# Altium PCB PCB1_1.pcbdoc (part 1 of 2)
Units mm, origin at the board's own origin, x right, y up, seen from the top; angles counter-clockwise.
Board outline 93.4 x 134 mm, 2 copper layers (Top Layer, Bottom Layer); 92 components, 71 nets, 349 pads, 191 vias.
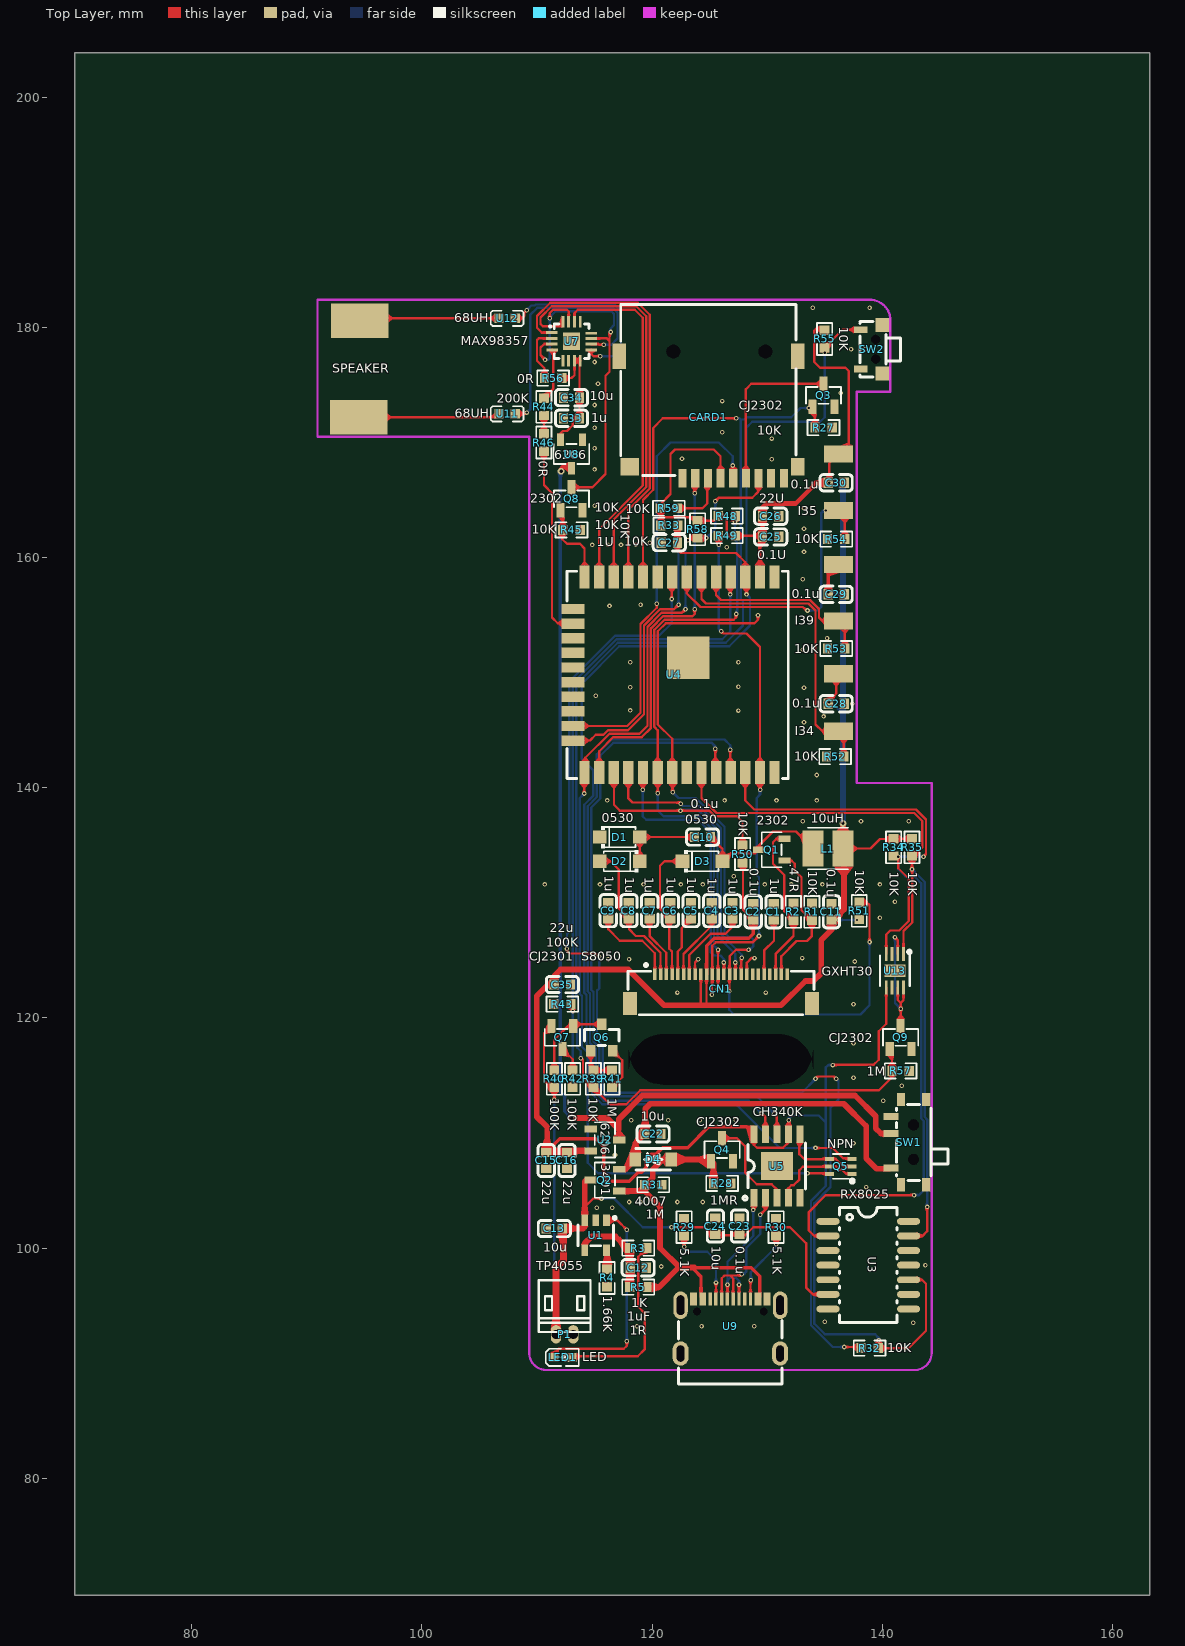
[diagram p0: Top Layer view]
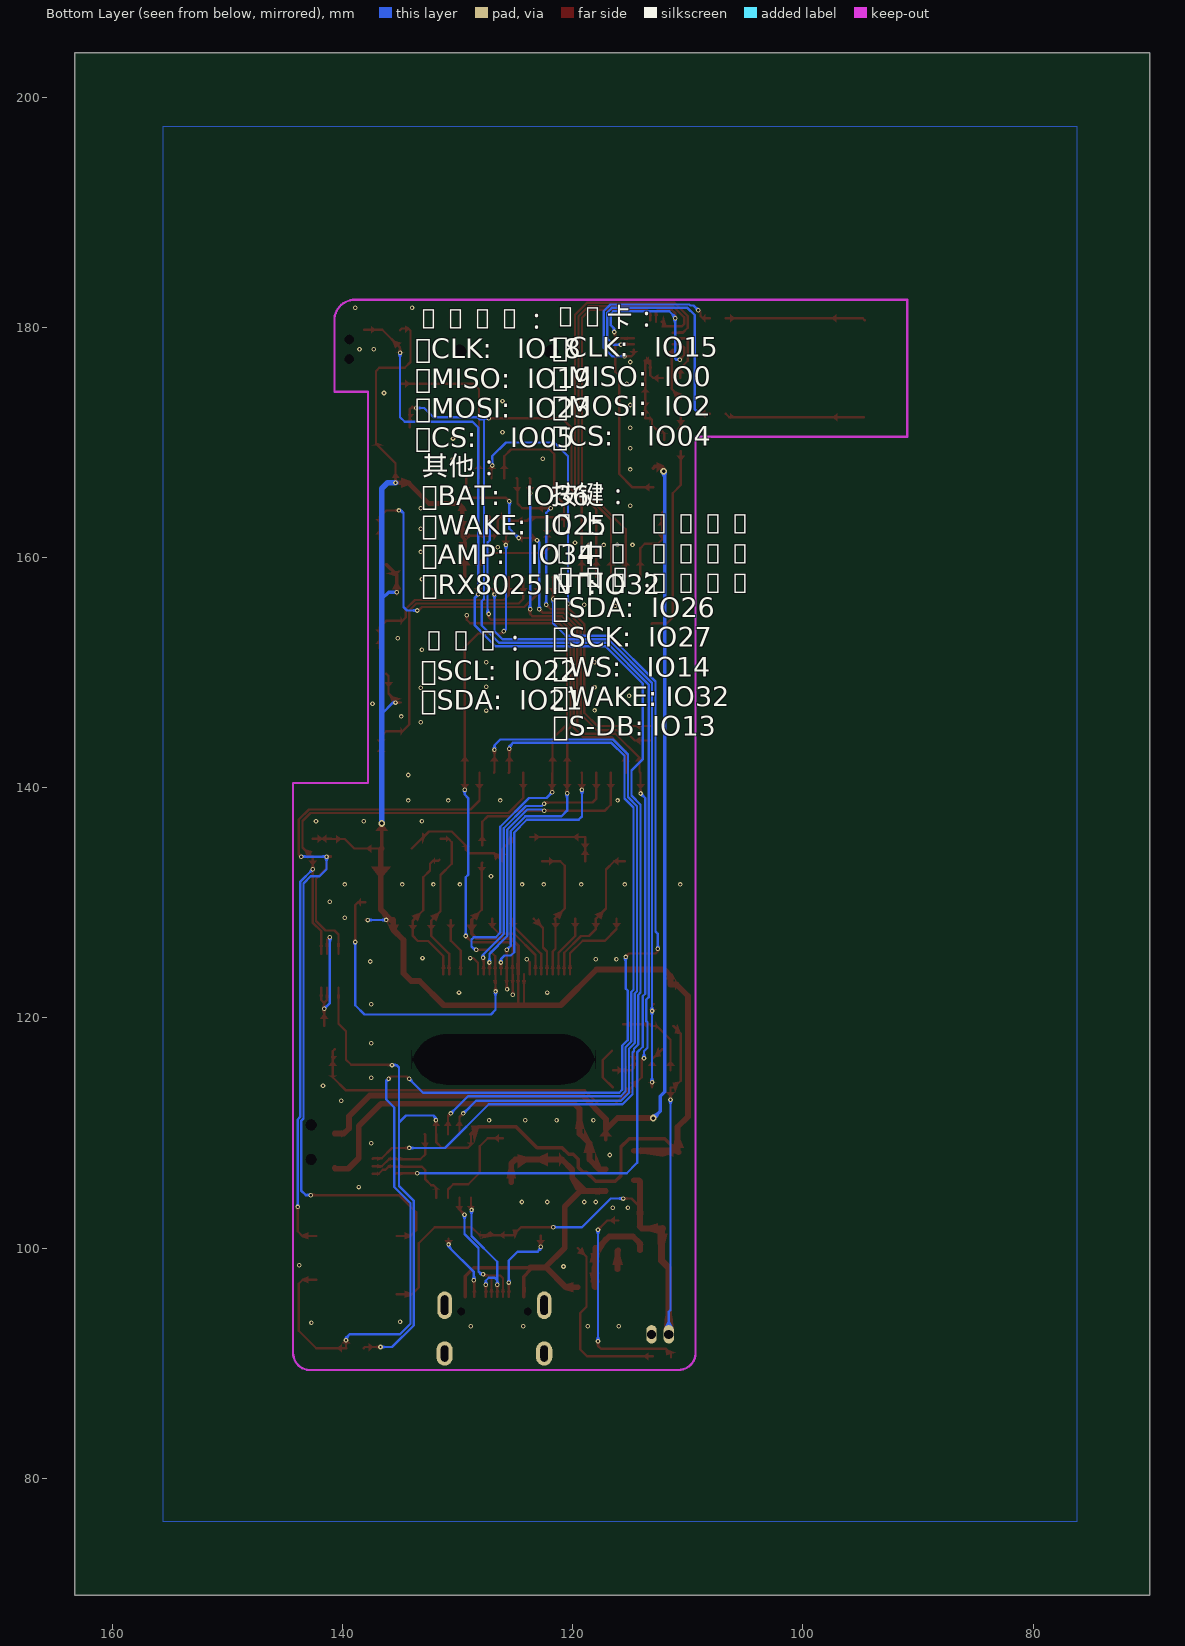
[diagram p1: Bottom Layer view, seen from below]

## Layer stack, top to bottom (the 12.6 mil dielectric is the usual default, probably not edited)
Top Layer: signal copper (thickness not stored)
Dielectric: dielectric 0.32, FR-4, Dk 4.8
Bottom Layer: signal copper (thickness not stored)

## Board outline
163.25,69.85 69.85,69.85 69.85,203.85 163.25,203.85
cut-out: 120.986,118.6 130.986,118.6 cw(c130.986,115.6) 133.986,115.6 133.986,117.2 cw(c130.986,117.2) 130.986,114.2 120.986,114.2 cw(c120.986,117.2) 117.986,117.2 117.986,115.6 cw(c120.986,115.6)

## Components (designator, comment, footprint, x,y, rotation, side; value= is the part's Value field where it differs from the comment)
C1 "CAP_0603" C0603 130.586,129.214 r270 top
C2 "CAP_0603" C0603 128.786,129.214 r270 top
C3 "CAP_0603" C0603 126.986,129.314 r270 top
C4 "CAP_0603" C0603 125.186,129.314 r270 top
C5 "CAP_0603" C0603 123.386,129.314 r270 top
C6 "CAP_0603" C0603 121.586,129.314 r270 top
C7 "CAP_0603" C0603 119.786,129.314 r270 top
C8 "CAP_0603" C0603 117.986,129.314 r270 top
C9 "CAP_0603" C0603 116.186,129.314 r270 top
C10 "CAP_0603" C0603 124.386,135.714 r180 top
C11 "CAP_0603" C0603 135.586,129.214 r270 top
C12 "CAP_0603" C0603 118.8,98.3 r0 top
C13 "CAP_0603" C0603 111.5,101.7 r180 top
C15 "CAP_0603" C0603 110.805,107.616 r90 top
C16 "CAP_0603" C0603 112.605,107.616 r90 top
C22 "CAP_0603" C0603 120.086,109.914 r180 top
C23 "CAP_0603" C0603 127.6,101.9 r270 top
C24 "CAP_0603" C0603 125.5,101.9 r270 top
C25 "CAP_0603" C0603 130.3,161.8 r180 top
C26 "CAP_0603" C0603 130.3,163.6 r180 top
C27 "CAP_0603" C0603 121.5,161.3 r0 top
C28 "CAP_0603" C0603 136,147.3 r0 top
C29 "CAP_0603" C0603 136,156.8 r0 top
C30 "CAP_0603" C0603 136,166.5 r0 top
C33 "CAP_0603" C0603 113,172.1 r0 top
C34 "CAP_0603" C0603 113,173.9 r0 top
C35 "CAP_0603" C0603 112.2,122.9 r180 top
CARD1 "XKTF-015-G" TF-SMD_XKTF-015-N 124.9,172.2 r180 top
CN1 "HW05150-240R00" FPC-SMD_24P-P0.50_HW05150-240R00 125.986,122.514 r0 top
D1 "MBR0530" SOD-123FL_L2.7-W1.8-LS3.7-RD 117.186,135.714 r0 top
D2 "MBR0530" SOD-123FL_L2.7-W1.8-LS3.7-RD 117.186,133.614 r180 top
D3 "MBR0530" SOD-123FL_L2.7-W1.8-LS3.7-RD 124.386,133.614 r0 top
D4 "SM4007PL_C64898" SOD-123F_L2.8-W1.8-LS3.7-RD 120.1,107.7 r0 top
L1 "SCCD32-100KT" IND-SMD_L3.5-W3.0 135.286,134.714 r0 top
LED1 "LED_0603-B" LED_0603 112.3,90.5 r0 top
P1 "弯针1.25*2" CON1.5*2-90 112.4,92.5 r180 top
Q1 "SL2302" SOT-23-3_L3.0-W1.7-P0.95-LS2.9-BR 130.386,134.614 r0 top
Q2 "CJ3401" SOT-23-3_L2.9-W1.6-P1.90-LS2.8-BR 115.9,105.9 r0 top
Q3 "CJ2302" SOT-23-3_L2.9-W1.3-P1.90-LS2.4-BR 134.9,174.1 r270 top
Q4 "CJ2302" SOT-23-3_L2.9-W1.3-P1.90-LS2.4-BR 126.085,108.547 r270 top
Q5 "PUMH9,115" SOT-363_L2.0-W1.3-P0.65-LS2.1-BL 136.4,107.1 r90 top
Q6 "S8050_SOT_NPN" S8050_SOT-23 115.5,118.3 r270 top
Q7 "CJ2301" SOT-23-3_L2.9-W1.3-P1.90-LS2.4-BR 112.2,118.3 r90 top
Q8 "CJ2302" SOT-23-3_L2.9-W1.3-P1.90-LS2.4-BR 113,165.1 r270 top
Q9 "CJ2302" SOT-23-3_L2.9-W1.3-P1.90-LS2.4-BR 141.6,118.3 r270 top
R1 "Res_0603" R0603 133.886,129.214 r270 top
R2 "Res_0603" R0603 132.286,129.214 r270 top
R3 "Res_0603" R0603 118.8,100 r0 top
R4 "Res_0603" R0603 116.1,97.4 r270 top
R5 "Res_0603" R0603 118.8,96.6 r180 top
R27 "Res_0603" R0603 134.9,171.3 r0 top
R28 "Res_0603" R0603 126.086,105.614 r180 top
R29 "Res_0603" R0603 122.786,101.814 r270 top
R30 "Res_0603" R0603 130.786,101.814 r90 top
R31 "Res_0603" R0603 120.1,105.5 r180 top
R32 "Res_0603" R0603 138.9,91.3 r180 top
R33 "Res_0603" R0603 121.5,162.8 r0 top
R34 "Res_0603" R0603 140.986,134.814 r270 top
R35 "Res_0603" R0603 142.586,134.814 r270 top
R39 "Res_0603" R0603 114.9,114.7 r90 top
R40 "Res_0603" R0603 111.5,114.7 r90 top
R41 "Res_0603" R0603 116.5,114.7 r270 top
R42 "Res_0603" R0603 113.1,114.7 r270 top
R43 "Res_0603" R0603 112.2,121.2 r180 top
R44 "Res_0603" R0603 110.6,173.1 r90 top
R45 "Res_0603" R0603 113,162.4 r180 top
R46 "Res_0603" R0603 110.6,170 r270 top
R48 "Res_0603" R0603 126.5,163.6 r0 top
R49 "Res_0603" R0603 126.5,161.9 r180 top
R50 "Res_0603" R0603 127.859,134.24 r90 top
R51 "Res_0603" R0603 138,129.3 r90 top
R52 "Res_0603" R0603 135.9,142.7 r180 top
R53 "Res_0603" R0603 136,152.1 r180 top
R54 "Res_0603" R0603 136,161.6 r180 top
R55 "Res_0603" R0603 135,179 r270 top
R56 "Res_0603" R0603 111.4,175.6 r180 top
R57 "Res_0603" R0603 141.6,115.4 r0 top
R58 "Res_0603" R0603 123.959,162.461 r270 top
R59 "Res_0603" R0603 121.459,164.287 r0 top
SW1 "MSK12CO2-BDM" SW-SMD_MSK12CO2-BDM 142.3,109.2 r90 top
SW2 "TS-1010-C-A" KEY-SMD_TX-1010-X-X 139.1,178.1 r270 top
U1 "TP4055" SOT-23-5_L3.0-W1.7-P0.95-LS2.8-BR 115.1,101.1 r90 top
U2 "ME6206A33M3G" SOT-23-3_L2.9-W1.6-P1.90-LS2.8-BR 115.9,109.4 r180 top
U3 "RX8025T-UB" SOIC-14_L10.1-W5.0-P1.27-LS7.4-BL 138.786,98.514 r270 top
U4 "ESP32-WROOM-32UE-N4_C2934568" WIFI-SMD_ESP32-WROOM-32UE-A 121.886,149.814 r270 top
U5 "CH340K" ESOP-10_L4.9-W3.9-P1.00-LS6.2-BL-EP 130.843,107.131 r0 top
U7 "MAX98357AETE+T" TQFN-16_L3.0-W3.0-P0.50-BL-EP1.5 113,178.8 r270 top
U8 "ME6206A33M3G" SOT-23-3_L2.9-W1.6-P1.90-LS2.8-BR 113,169 r90 top
U9 "TYPE-C16PIN母座 板上四脚三次molding" USB-SMD_TYPE-C16PIN 126.8,93.2 r0 top
U11 "EBLS1608-3R9K" L0603 107.4,172.5 r180 top
U12 "EBLS1608-3R9K" L0603 107.4,180.8 r180 top
U13 "GXHT30" DFN-8_L2.5-W2.5-P0.50-BL-EP 141.1,124.1 r180 top

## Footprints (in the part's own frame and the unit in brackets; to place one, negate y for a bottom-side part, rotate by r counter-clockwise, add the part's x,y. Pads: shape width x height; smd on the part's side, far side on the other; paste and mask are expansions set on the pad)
C0603 [mm]
  rect 0.8x0.9 smd paste+0 mask+0.051: 1(-0.7,0) 2(0.7,0)
  silkscreen extent -1.41,-0.71 1.39,0.72
CON1.5*2-90 [mm]
  oval 0.9x1.6 hole 0.8 paste+0 mask+0.102: 1(-0.75,0) 2(0.75,0)
  silkscreen extent -2.25,-4.7 2.25,-0.2
DFN-8_L2.5-W2.5-P0.50-BL-EP [mm]
  rect 0.25x1.25 smd paste+0 mask+0.051: 1(-0.75,-1.454) 2(-0.25,-1.454) 3(0.25,-1.454) 4(0.75,-1.454) 5(0.75,1.454) 6(0.25,1.454) 7(-0.25,1.454) 8(-0.75,1.454)
  rect 1.8x1.1 smd paste+0 mask+0.051: 9(0,0)
  silkscreen extent -1.39,-1.77 1.3,1.3
ESOP-10_L4.9-W3.9-P1.00-LS6.2-BL-EP [mm]
  rect 0.6x1.5 smd paste+0 mask+0.051: 1(-2,-2.75) 2(-1,-2.75) 3(0,-2.75) 4(1,-2.75) 5(2,-2.75) 6(2,2.75) 7(1,2.75) 8(0,2.75) 9(-1,2.75) 10(-2,2.75)
  rect 2.8x2.4 smd paste+0 mask+0.051: 11(0,0)
  silkscreen extent -2.94,-2.96 2.5,2
FPC-SMD_24P-P0.50_HW05150-240R00 [mm]
  rect 0.3x1 smd paste+0 mask+0.05: 1(-5.75,1.275) 2(-5.25,1.275) 3(-4.75,1.275) 4(-4.25,1.275) 5(-3.75,1.275) 6(-3.25,1.275) 7(-2.75,1.275) 8(-2.25,1.275) 9(-1.75,1.275) 10(-1.25,1.275) 11(-0.75,1.275) 12(-0.25,1.275) 13(0.25,1.275) 14(0.75,1.275) 15(1.25,1.275) 16(1.75,1.275) 17(2.25,1.275) 18(2.752,1.275) 19(3.25,1.275) 20(3.75,1.275) 21(4.25,1.275) 22(4.75,1.275) 23(5.25,1.275) 24(5.75,1.275)
  rect 1.2x2 smd paste+0 mask+0.05: 25(7.9,-1.275) 26(-7.9,-1.275)
  silkscreen extent -8.09,-2.24 8.07,2.21
IND-SMD_L3.5-W3.0 [mm]
  rect 1.8x3.12 smd paste+0 mask+0.051: 1(1.303,0) 2(-1.303,0)
  silkscreen extent -1.75,-1.8 1.75,1.8
KEY-SMD_TX-1010-X-X [mm]
  rect 0.6x1.2 smd paste+0 mask+0.051: 1(-1.7,-0.975) 2(1.7,-0.975)
  rect 1.2x1.3 smd paste+0 mask+0.051: 3(-2.1,0.975) 4(2.1,0.975)
  Multi-Layer board cut-out: -0.85,0.725 -1.023,0.685 -1.163,0.574 -1.24,0.414 -1.24,0.236 -1.163,0.076 -1.023,-0.035 -0.85,-0.075 -0.85,-0.075 -0.676,-0.035 -0.537,0.076 -0.46,0.236 -0.46,0.414 -0.537,0.574 -0.676,0.685 -0.85,0.725
  Multi-Layer board cut-out: 0.85,0.725 0.677,0.685 0.537,0.574 0.46,0.414 0.46,0.236 0.537,0.076 0.677,-0.035 0.85,-0.075 0.85,-0.075 1.024,-0.035 1.163,0.076 1.24,0.236 1.24,0.414 1.163,0.574 1.024,0.685 0.85,0.725
  silkscreen extent -2.4,-1.03 2.4,2.48
L0603 [mm]
  rect 0.8x0.864 smd paste-100 mask+0.051: 1(-0.7,0) 2(0.7,0)
  silkscreen extent -1.42,-0.65 1.41,0.67
LED_0603 [mil]
  rect 31.5x31.5 smd paste+0 mask+2: 1(-33.5,-0.4) 2(29.5,-0.2)
  silkscreen extent -61,-30 53,30
R0603 [mm]
  rect 0.806x0.864 smd paste-100 mask+0.051: 1(-0.753,0) 2(0.753,0)
  silkscreen extent -1.39,-0.66 1.39,0.66
S8050_SOT-23 [mm]
  rect 1x0.8 smd paste+0 mask+0.051: 1(1.15,-0.823) 2(1.15,1.077) 3(-1.15,0.127)
  silkscreen extent -0.7,-1.37 0.7,1.63
SOD-123F_L2.8-W1.8-LS3.7-RD [mm]
  rect 1x1.2 smd paste+0 mask+0.051: 1(-1.55,0) 2(1.55,0)
  silkscreen extent -1.52,-0.93 1.49,0.95
SOD-123FL_L2.7-W1.8-LS3.7-RD [mm]
  rect 1.2x1.15 smd paste+0 mask+0.051: 1(-1.735,0) 2(1.735,0)
  silkscreen extent -1.6,-0.95 1.38,0.95
SOIC-14_L10.1-W5.0-P1.27-LS7.4-BL [mm]
  oval 0.6x2 smd paste+0 mask+0.051: 1(-3.81,-3.5) 2(-2.54,-3.5) 3(-1.27,-3.5) 4(0,-3.5) 5(1.27,-3.5) 6(2.54,-3.5) 7(3.81,-3.5) 8(3.81,3.5) 9(2.54,3.5) 10(1.27,3.5) 11(0,3.5) 12(-1.27,3.5) 13(-2.54,3.5) 14(-3.81,3.5)
  silkscreen extent -5,-2.5 5,2.5
SOT-23-3_L2.9-W1.3-P1.90-LS2.4-BR [mm]
  rect 1.25x0.7 smd paste+0 mask+0.051: 1(1,-0.95) 2(1,0.95) 3(-1,0)
  silkscreen extent -0.73,-1.53 0.73,1.53
SOT-23-3_L2.9-W1.6-P1.90-LS2.8-BR [mm]
  rect 1.07x0.6 smd paste+0 mask+0.051: 1(1.235,-0.95) 2(1.235,0.95) 3(-1.235,0)
  silkscreen extent -0.88,-1.54 0.88,1.54
SOT-23-3_L3.0-W1.7-P0.95-LS2.9-BR [mm]
  rect 1.037x0.532 smd paste+0 mask+0.051: 1(1.101,-0.95) 2(1.101,0.95) 3(-1.101,0)
  silkscreen extent -0.86,-1.53 0.86,1.53
SOT-23-5_L3.0-W1.7-P0.95-LS2.8-BR [mm]
  rect 1x0.6 smd paste+0 mask+0.051: 1(1.3,-0.95) 2(1.3,0) 3(1.3,0.95) 4(-1.3,0.95) 5(-1.3,-0.95)
  silkscreen extent -0.9,-1.78 1.65,1.55
SOT-363_L2.0-W1.3-P0.65-LS2.1-BL [mm]
  rect 0.35x0.78 smd paste+0 mask+0.051: 1(-0.65,-0.99) 2(0,-0.99) 3(0.65,-0.99) 4(0.65,0.99) 5(0,0.99) 6(-0.65,0.99)
  silkscreen extent -1.43,-1.14 1.08,0.7
SW-SMD_MSK12CO2-BDM [mm]
  rect 0.6x1.3 smd paste+0 mask+0.051: 1(2.25,1.525) 2(0.75,1.525) 3(-2.25,1.525)
  rect 1.15x0.7 smd paste+0 mask+0.051: 4(-3.7,-1.525) 4(-3.7,0.675) 4(3.7,-1.525) 4(3.7,0.675)
  Multi-Layer board cut-out: -1.5,-0.9 -1.294,-0.853 -1.129,-0.721 -1.037,-0.531 -1.037,-0.319 -1.129,-0.129 -1.294,0.003 -1.5,0.05 -1.5,0.05 -1.706,0.003 -1.871,-0.129 -1.963,-0.319 -1.963,-0.531 -1.871,-0.721 -1.706,-0.853 -1.5,-0.9
  Multi-Layer board cut-out: 1.5,-0.9 1.706,-0.853 1.871,-0.721 1.963,-0.531 1.963,-0.319 1.871,-0.129 1.706,0.003 1.5,0.05 1.5,0.05 1.294,0.003 1.129,-0.129 1.037,-0.319 1.037,-0.531 1.129,-0.721 1.294,-0.853 1.5,-0.9
  silkscreen extent -3.33,-3.42 3.27,1.08
TF-SMD_XKTF-015-N [mm]
  rect 0.7x1.6 smd paste+0 mask+0.051: 1(2.25,5.3) 2(1.15,5.3) 3(0.05,5.3) 4(-1.05,5.3) 5(-2.15,5.3) 6(-3.25,5.3) 7(-4.35,5.3) 8(-5.45,5.3) 9(-6.55,5.3)
  rect 1.2x1.5 smd paste+0 mask+0.051: 10(-7.75,4.3)
  rect 1.2x2.2 smd paste+0 mask+0.051: 11(-7.75,-5.3) 13(7.75,-5.3)
  rect 1.6x1.5 smd paste+0 mask+0.051: 12(6.85,4.3)
  Multi-Layer board cut-out: 2.45,-5.7 2.509,-5.96 2.676,-6.169 2.917,-6.285 3.184,-6.285 3.424,-6.169 3.591,-5.96 3.65,-5.7 3.65,-5.7 3.591,-5.44 3.424,-5.231 3.184,-5.115 2.917,-5.115 2.676,-5.231 2.509,-5.44 2.45,-5.7
  Multi-Layer board cut-out: -5.55,-5.7 -5.491,-5.96 -5.324,-6.169 -5.083,-6.285 -4.816,-6.285 -4.576,-6.169 -4.409,-5.96 -4.35,-5.7 -4.35,-5.7 -4.409,-5.44 -4.576,-5.231 -4.816,-5.115 -5.083,-5.115 -5.324,-5.231 -5.491,-5.44 -5.55,-5.7
  silkscreen extent -7.62,-9.78 7.62,5.08
TQFN-16_L3.0-W3.0-P0.50-BL-EP1.5 [mm]
  rect 0.25x1 smd mask+0.051: 1(-0.75,-1.7) 2(-0.249,-1.7) 3(0.252,-1.7) 4(0.752,-1.683) 9(0.75,1.7) 10(0.25,1.7) 11(-0.25,1.7) 12(-0.7,1.7)
  rect 1x0.25 smd mask+0.051: 5(1.716,-0.748) 6(1.7,-0.248) 7(1.7,0.252) 8(1.7,0.752) 13(-1.7,0.752) 14(-1.7,0.252) 15(-1.7,-0.248) 16(-1.7,-0.748)
  rect 1.5x1.5 smd paste-100 mask+0.051: 17(0,0)
  silkscreen extent -1.5,-1.9 1.5,1.5
USB-SMD_TYPE-C16PIN [mm]
  oval 1.25x2.4 hole 0.65 slot 1.7 at 90 deg paste+0 mask+0.05: 17(-4.325,1.835) 18(4.325,1.835)
  oval 1.4x2.1 hole 0.65 slot 1.4 at 90 deg paste+0 mask+0.05: 19(-4.325,-2.365) 20(4.325,-2.365)
  rect 0.3x1.15 smd paste-100 mask+0.05: A1(-3.35,2.365) A4(-2.55,2.365) A5(-1.25,2.365) A6(-0.25,2.365) A7(0.25,2.365) A8(1.25,2.365) A9(2.55,2.365) A12(3.35,2.365) B1(3.05,2.365) B4(2.25,2.365) B5(1.75,2.365) B6(0.75,2.365) B7(-0.75,2.365) B8(-1.75,2.365) B9(-2.25,2.365) B12(-3.05,2.365)
  Multi-Layer board cut-out: -2.575,1.285 -2.607,1.426 -2.697,1.539 -2.828,1.602 -2.972,1.602 -3.103,1.539 -3.193,1.426 -3.225,1.285 -3.225,1.285 -3.193,1.144 -3.103,1.031 -2.972,0.968 -2.828,0.968 -2.697,1.031 -2.607,1.144 -2.575,1.285
  Multi-Layer board cut-out: 3.225,1.285 3.193,1.426 3.103,1.539 2.972,1.602 2.828,1.602 2.697,1.539 2.607,1.426 2.575,1.285 2.575,1.285 2.607,1.144 2.697,1.031 2.828,0.968 2.972,0.968 3.103,1.031 3.193,1.144 3.225,1.285
  silkscreen extent -4.5,-5.01 4.5,0.52
WIFI-SMD_ESP32-WROOM-32UE-A [mm]
  rect 2x0.9 smd paste+0 mask+0.051: 1(-8.5,8.755) 2(-8.5,7.485) 3(-8.5,6.215) 4(-8.5,4.945) 5(-8.5,3.675) 6(-8.5,2.405) 7(-8.5,1.135) 8(-8.5,-0.135) 9(-8.5,-1.405) 10(-8.5,-2.675) 11(-8.5,-3.945) 12(-8.5,-5.215) 13(-8.5,-6.485) 14(-8.5,-7.755) 25(8.5,-7.755) 26(8.5,-6.485) 27(8.5,-5.215) 28(8.5,-3.945) 29(8.5,-2.675) 30(8.5,-1.405) 31(8.5,-0.135) 32(8.5,1.135) 33(8.5,2.405) 34(8.5,3.675) 35(8.5,4.945) 36(8.5,6.215) 37(8.5,7.485) 38(8.5,8.755)
  rect 0.9x2 smd paste+0 mask+0.051: 15(-5.715,-8.755) 16(-4.445,-8.755) 17(-3.175,-8.755) 18(-1.905,-8.755) 19(-0.635,-8.755) 20(0.635,-8.755) 21(1.905,-8.755) 22(3.175,-8.755) 23(4.445,-8.755) 24(5.715,-8.755)
  rect 3.7x3.7 smd paste+0 mask+0.051: 39(-1.5,1.255)
  silkscreen extent -9,-9.27 9.02,9.95

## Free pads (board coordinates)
  rect 5x3 smd mask+0.051: 1(94.5,172.2) 1(94.6,180.6)
  rect 2.5x1.5 smd mask+0.051: 1(136.2,144.9) 1(136.2,149.9) 1(136.2,154.5) 1(136.2,159.4) 1(136.2,164.1) 1(136.2,169)

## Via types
v1: diameter 0.4, hole 0.2, Top Layer to Bottom Layer, 188 vias
v2: diameter 0.6, hole 0.3, Top Layer to Bottom Layer, 3 vias

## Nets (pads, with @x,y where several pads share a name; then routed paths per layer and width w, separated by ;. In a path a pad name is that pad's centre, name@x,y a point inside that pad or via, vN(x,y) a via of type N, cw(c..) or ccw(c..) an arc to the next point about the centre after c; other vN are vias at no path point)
3V3: C2.2 C11.2 C15.2 C16.2 C25.2 C26.2 C28.1 C29.1 C30.1 C35.2 CARD1.4 CN1.9 CN1.10 L1.1 pad.1@136.2,149.9 pad.1@136.2,159.4 pad.1@136.2,169 R32.2 R33.1 R34.1 R35.1 R48.1 R49.1 R50.1 R51.1 R55.1 R58.1 R59.1 U2.2 U4.2 U5.7 U5.10 U13.5 | length 255.5
  Top Layer w0.2: R33.1@120.747,162.7 120.747,163.507 ; 124.206,121.1 124.235,121.129 CN1.9@124.235,123.789 ; 124.685,121.1 124.736,121.151 CN1.10@124.736,123.789 ; CARD1.4@125.95,166.9 125.95,168.8 125.35,169.4 122,169.4 121.6,169 121.6,165.518 120.747,164.665 120.747,163.507 ; R50.1@127.859,133.487 127.9,133.445 127.9,129.4 C2.2@128.786,128.514 ; U5.10@128.843,109.881 128.843,108.98 129.109,108.714 131.386,108.714 131.843,109.172 U5.7@131.843,109.881 131.886,109.923 v1(131.886,111.114) ; C25.2@129.6,161.8 129.5,161.9 R49.1@127.253,161.9 126.7,161.9 126.5,162.1 126.5,163.364 126.264,163.6 R48.1@125.747,163.6 125.361,163.214 R58.1@123.959,163.214 123.666,163.507 120.747,163.507 ; C28.1@134.939,147.4 v1(135.4,147.4) 135.4,147.6 136,148.2 136,149.7 pad.1@136.2,149.9 ; R55.1@135,179.753 134.853,179.9 134.281,179.9 134.1,179.719 134.1,177 134.6,176.5 136.8,176.5 137.1,176.2 137.1,169.9 pad.1@136.2,169 135.4,168.2 v1(135.4,166.5) ; C29.1@135.3,156.8 v1(135.3,157) ; v1(135.7,115.9) 135.72,115.92 139.25,115.92 139.7,116.37 139.7,118.846 140.35,119.496 U13.5@140.35,122.646 ; C11.2@135.786,128.514 v1(136.2,128.514) ; L1.1@136.589,134.714 138.986,134.714 139.812,135.541 140.958,135.541 R34.1@140.986,135.568 R35.1@142.586,135.568 ; v1(136.7,91.4) 138.047,91.4 R32.2@138.147,91.3 ; v1(137.8,128.5) 137.953,128.5 R51.1@138,128.547
  Top Layer w0.3: C15.2@110.94,108.45 111.99,109.5 115.1,109.5 115.8,108.8 115.8,106.3 116.3,105.8 118,105.8 118.8,106.6 119.1,106.6 119.5,107 119.5,107.7 119.936,108.136 120.336,108.136 120.927,108.727 123.1,108.727 124.933,110.56 128.164,110.56 U5.10@128.843,109.881 ; CN1.10@124.736,123.789 124.736,126.264 125.386,126.914 128.386,126.914 128.786,127.314 C2.2@128.786,128.514 ; U4.2@129.371,158.315 129.371,161.571 C25.2@129.6,161.8 C26.2@129.6,163.6 ; v1(135.3,157) 135.3,158.5 pad.1@136.2,159.4 ; L1.1@136.589,134.714 v2(136.589,136.9)
  Top Layer w0.4: C26.2@129.6,163.6 129.6,164.4 129.9,164.7 132.5,164.7 134.2,166.4 134.2,166.5 v1(135.4,166.5)
  Top Layer w0.5: C15.2@110.805,108.316 110.94,108.45 U2.2@114.665,108.45 ; C15.2@110.886,108.396 110.886,110.514 109.986,111.414 109.986,121.914 110.971,122.9 C35.2@111.5,122.9 111.5,123.651 112.049,124.2 117.936,124.2 121.036,121.1 124.206,121.1 124.685,121.1 131.208,121.1 133.323,123.214 134.03,123.214 134.695,123.88 134.695,126.768 135.586,127.659 C11.2@135.586,128.514 135.786,128.514 136.686,129.414 136.686,134.617 L1.1@136.589,134.714
  Bottom Layer w0.2: v1(131.886,111.114) 131.886,111.314 132.086,111.514 134.486,111.514 135.1,110.9 ; v1(135.4,147.4) 135.606,147.4 136.589,146.417 ; v1(135.7,115.9) 135.3,115.9 135.1,115.7 135.1,110.9 ; v1(136.2,128.514) 136.214,128.5 v1(137.8,128.5) ; v1(136.7,91.4) 135.7,91.4 133.8,93.3 133.8,104.1 135.1,105.4 135.1,110.9
  Bottom Layer w0.3: v1(135.3,157) 136,157 136.589,156.411
  Bottom Layer w0.5: v1(135.4,166.5) 136.1,166.5 136.589,166.011 136.589,156.411 136.589,146.417 v2(136.589,136.9)
8025INT: R32.1 U3.10 U4.8 | length 114.2
  Top Layer w0.2: v1(112.6,126) 112.6,125.8 112.8,125.6 115.1,125.6 v1(115.4,125.3) ; v1(121.7,156.4) 121.7,158.264 U4.8@121.751,158.315 ; v1(134.2,114.7) 134.4,114.9 135.8,114.9 v1(136,114.7) ; v1(139.7,92) 139.7,91.347 R32.1@139.653,91.3 142.286,91.3 143.8,92.814 143.8,96.9 143.456,97.244 U3.10@142.286,97.244
  Bottom Layer w0.2: v1(112.6,126) 112.6,127.302 112.798,127.5 112.798,149.225 116.775,153.202 120.602,153.202 121.7,154.3 v1(121.7,156.4) ; v1(115.4,125.3) 115.4,122.561 115.21,122.371 115.21,118.071 115.706,117.575 115.706,113.748 115.952,113.502 133.002,113.502 v1(134.2,114.7) ; 134.102,103.9 134.102,93.425 135.014,92.514 139.386,92.514 139.7,92.2 v1(139.7,92) ; 134.102,103.902 135.5,105.3 135.5,112.207 136.2,112.907 136.2,114.5 v1(136,114.7)
$1N246: C1.2 CN1.20 | length 5.1
  Top Layer w0.2: CN1.20@129.736,123.789 129.736,125.864 130.586,126.714 C1.2@130.586,128.514
$1N372: C3.2 CN1.7 | length 7.1
  Top Layer w0.2: CN1.7@123.235,123.789 123.235,125.464 125.083,127.312 126.386,127.312 126.986,127.912 C3.2@126.986,128.614
$1N423: C4.2 CN1.6 | length 5.8
  Top Layer w0.2: CN1.6@122.736,123.789 122.736,125.564 125.186,128.014 C4.2@125.186,128.614
$1N427: C5.2 CN1.5 | length 5.3
  Top Layer w0.2: CN1.5@122.235,123.789 122.235,125.764 122.586,126.114 122.586,127.814 C5.2@123.386,128.614
$1N505: C7.2 CN1.3 | length 5.4
  Top Layer w0.2: C7.2@119.786,128.614 119.786,127.114 121.235,125.665 CN1.3@121.235,123.789
$1N562: C9.2 CN1.1 | length 7.6
  Top Layer w0.2: C9.2@116.186,128.614 116.186,127.714 117.186,126.714 119.135,126.714 120.235,125.614 CN1.1@120.235,123.789
$1N900: C10.2 D1.2 D2.1 | length 6.9
  Top Layer w0.2: D2.1@118.921,133.614 D1.2@118.921,135.714 C10.2@123.686,135.714
$1N1154: C10.1 D3.2 L1.2 Q1.3 | length 12.3
  Top Layer w0.2: C10.1@125.086,135.714 126.121,134.679 D3.2@126.121,133.614 126.806,134.3 128.97,134.3 Q1.3@129.284,134.614 129.284,134.984 130.5,136.2 132.497,136.2 L1.2@133.983,134.714
$1N1499: LED1.1 U1.1 | length 19.1
  Top Layer w0.2: LED1.1@111.449,90.49 111.449,90.79 111.9,91.241 117.541,91.241 117.8,91.5 v1(117.8,91.9) ; U1.1@116.05,102.4 117,102.4 v1(117.8,101.6)
  Bottom Layer w0.2: v1(117.8,91.9) v1(117.8,101.6)
$1N1521: LED1.2 R3.2 | length 15.9
  Top Layer w0.2: LED1.2@113.049,90.595 118.749,90.595 119.349,91.195 119.349,94.351 118.8,94.9 118.8,99.247 R3.2@119.553,100
$1N1592: R4.1 U1.5 | length 1.7
  Top Layer w0.5: U1.5@116.05,99.8 116.1,99.75 R4.1@116.1,98.153
$1N2827: CARD1.6 Q3.3 | length 14.7
  Top Layer w0.2: CARD1.6@128.15,166.9 128.15,174.63 128.62,175.1 Q3.3@134.9,175.1
$1N3650: Q4.3 U5.3 | length 8.7
  Top Layer w0.2: Q4.3@126.085,109.547 127.386,109.547 128.085,108.848 128.085,106.547 129.085,105.547 130.385,105.547 130.843,105.088 U5.3@130.843,104.381
$1N5042: R29.2 U9.A5 | length 7.5
  Top Layer w0.2: v1(122.786,100.114) R29.2@122.786,101.061 ; U9.A5@125.55,95.757 v1(125.55,97)
  Bottom Layer w0.2: v1(122.786,100.114) 122.786,99.914 123.029,99.671 124.802,99.671 125.55,98.922 v1(125.55,97)
  other v1: 125.55,97
$1N5135: R30.1 U9.B5 | length 6
  Top Layer w0.2: U9.B5@128.55,95.757 128.55,97.179 v1(128.586,97.214) ; v1(130.786,100.314) R30.1@130.786,100.812
  Bottom Layer w0.2: v1(128.586,97.214) 128.586,97.914 130.786,100.114 v1(130.786,100.314)
$1N9174: Q6.1 R39.2 R41.1 | length 3.4
  Top Layer w0.2: Q6.1@114.677,117.15 114.677,115.676 R39.2@114.9,115.453 R41.1@116.5,115.453
$1N9291: Q6.3 Q7.1 R40.2 | length 7.3
  Top Layer w0.2: R40.2@111.5,115.453 111.5,118.1 112.7,119.3 Q7.1@113.15,119.3 113.3,119.45 Q6.3@115.627,119.45
$1N9318: Q7.3 R42.1 | length 2.2
  Top Layer w0.2: Q7.3@112.2,117.3 113.1,116.4 R42.1@113.1,115.453
$2N220: R44.2 U7.4 | length 4.6
  Top Layer w0.2: R44.2@110.6,173.853 111.4,174.653 111.4,177.966 U7.4@111.317,178.049
$2N1483: R56.2 U7.2 | length 4.9
  Top Layer w0.2: R56.2@110.647,175.6 110.647,176.453 110,177.1 110,178.9 110.149,179.049 U7.2@111.3,179.049
$2N1555: U7.10 U11.1 | length 22.5
  Top Layer w0.2: U11.1@108.1,172.5 109,172.5 v1(109.1,172.6) ; U7.10@114.7,178.55 115.351,178.55 115.401,178.5 v1(115.8,178.5)
  Bottom Layer w0.2: v1(109.1,172.6) 109.4,172.9 109.4,181.08 110.02,181.7 116.6,181.7 116.998,181.302 116.998,179.048 116.45,178.5 v1(115.8,178.5)
$2N1588: U7.9 U12.1 | length 16.6
  Top Layer w0.2: U12.1@108.1,180.8 108.7,180.8 108.9,181 108.9,181.3 v1(109.1,181.5) ; U7.9@114.7,178.05 114.7,177.7 114.9,177.5 v1(115.5,177.5)
  Bottom Layer w0.2: v1(109.1,181.5) 109.5,181.9 109.793,181.9 109.895,182.002 116.725,182.002 117.3,181.427 117.3,178.223 116.577,177.5 v1(115.5,177.5)
$4N231: Q9.3 U13.2 U13.7 U13.8 | length 12.9
  Top Layer w0.2: v1(141.1,127) 141.35,126.75 U13.2@141.35,125.554 ; U13.7@141.35,122.646 141.35,121.55 141.6,121.3 ; Q9.3@141.6,119.3 v1(141.6,120.8) 141.6,121.3 ; U13.8@141.85,122.646 141.85,121.55 141.6,121.3
  Bottom Layer w0.2: v1(141.1,127) 141.1,121.3 v1(141.6,120.8)
  other v1: 141.1,127
ADC-BAT: R42.2 R43.1 U4.4 | length 56.1
  Top Layer w0.2: R43.1@112.953,121.2 113.1,121.053 v1(113.1,120.6) ; R42.2@113.1,113.947 v1(113.1,114.4) ; v1(126.8,156.8) 126.8,158.284 U4.4@126.831,158.315
  Bottom Layer w0.2: v1(113.1,114.4) v1(113.1,120.6) 113.1,149.1 116.9,152.9 126.1,152.9 126.8,153.6 v1(126.8,156.8)
BUSY: CN1.16 U4.28 | length 24.8
  Top Layer w0.2: U4.28@117.941,141.314 117.941,139.059 118.286,138.714 122.386,138.714 v1(122.486,138.614) ; CN1.16@127.736,123.789 127.736,125.164 v1(127.786,125.214)
  Bottom Layer w0.2: v1(122.486,138.614) 122.686,138.414 124.067,138.414 125.992,136.49 125.992,127.291 127.786,125.497 v1(127.786,125.214)
CLK: CN1.12 R48.2 U4.30 | length 51.9
  Top Layer w0.2: v1(120.486,139.514) 120.486,141.309 U4.30@120.481,141.314 120.481,144.992 120.198,145.275 120.198,153.725 121.073,154.6 127.1,154.6 127.3,154.8 v1(127.3,155.1) ; v1(125.7,122.5) 125.736,122.536 CN1.12@125.736,123.789 v1(125.736,125.914) ; v1(127.2,163.1) 127.2,163.547 R48.2@127.253,163.6
  Bottom Layer w0.2: v1(120.486,139.514) 120.486,138.014 120.984,137.516 124.111,137.516 125.388,136.239 125.388,126.262 v1(125.736,125.914) ; v1(127.2,163.1) 127.2,161.5 127.398,161.302 127.398,155.198 v1(127.3,155.1)
CS: CN1.13 U4.29 | length 23.4
  Top Layer w0.2: v1(119.196,139.814) 119.196,141.3 U4.29@119.211,141.314 ; CN1.13@126.235,123.789 v1(126.235,124.814)
  Bottom Layer w0.2: v1(119.196,139.814) 119.196,137.504 119.486,137.214 123.986,137.214 125.086,136.114 125.086,125.714 125.386,125.414 125.935,125.414 126.235,125.114 v1(126.235,124.814)
DATA+: U5.1 U9.A6 U9.B6 | length 12.2
  Top Layer w0.2: U9.A6@126.55,95.757 v1(126.55,96.814) ; U9.B6@127.55,95.757 v1(127.55,96.814) ; v1(128.786,103.314) 128.843,103.372 U5.1@128.843,104.381
  Bottom Layer w0.2: v1(126.55,96.814) 126.55,97.179 ; v1(127.55,96.814) 127.55,97.15 127.286,97.414 126.786,97.414 126.55,97.179 ; v1(128.786,103.314) 128.786,101.042 126.55,98.806 126.55,97.179
DATA-: U5.2 U9.A7 U9.B7 | length 13.1
  Top Layer w0.2: U9.B7@126.05,95.757 126.05,97.379 126.286,97.614 126.786,97.614 ; U9.A7@127.05,95.757 127.05,97.35 126.786,97.614 ; v1(127.786,97.714) 127.686,97.614 126.786,97.614 ; v1(129.4,102.9) 129.843,103.343 U5.2@129.843,104.381
  Bottom Layer w0.2: v1(127.786,97.714) 127.958,97.714 128.186,97.942 128.186,100.014 129.4,101.229 v1(129.4,102.9)
DC: CN1.14 R51.2 U4.31 | length 71.9
  Top Layer w0.2: v1(121.786,139.614) 121.786,141.279 U4.31@121.751,141.314 121.751,144.249 120.5,145.5 120.5,153.6 121.198,154.298 128.898,154.298 129.2,154.6 v1(129.2,155) ; v1(126.7,122.3) 126.7,123.754 CN1.14@126.736,123.789 126.736,125.364 127.286,125.914 v1(128.386,125.914) ; R51.2@138,130.053 138.647,130.053 138.9,129.8 v1@138.9,126.5
  Bottom Layer w0.2: v1(121.786,139.614) 122.284,139.116 123.792,139.116 126.294,136.615 126.294,127.416 126.696,127.014 128.586,127.014 128.786,126.814 128.786,126.214 128.486,125.914 v1(128.386,125.914) ; v1(126.7,122.3) 126.7,120.7 127.098,120.302 132.6,120.302 132.602,120.3 138.1,120.3 138.9,121.1 v1(138.9,126.6)
DIN: CN1.11 R49.2 U4.37 | length 46.4
  Top Layer w0.2: v1(125.2,122) 125.2,123.754 CN1.11@125.235,123.789 125.235,126.266 125.531,126.562 128.734,126.562 v1(129.286,127.114) ; R49.2@125.747,161.9 125.8,161.847 v1(125.8,161.1) ; v1(126,153.6) 126.2,153.4 128.2,153.4 129.371,152.229 U4.37@129.371,141.314 129.371,139.829 v1(129.386,139.814)
  Bottom Layer w0.2: v1(125.8,161.1) 125.8,153.8 v1(126,153.6) ; v1(129.286,127.114) 129.286,132.214 129.088,132.412 129.088,139.116 129.386,139.414 v1(129.386,139.814)
DTR: Q5.1 Q5.5 U5.4 | length 7.9
  Top Layer w0.2: U5.4@131.843,104.381 131.843,105.205 132.099,105.461 132.299,105.461 132.799,105.961 132.799,106.761 133.099,107.061 135.371,107.061 Q5.5@135.41,107.1 135.973,107.1 136.275,106.798 136.501,106.798 136.849,106.45 Q5.1@137.39,106.45
EN: C27.2 Q5.3 R33.2 R55.2 SW2.1 U4.3 | length 123.9
  Top Layer w0.2: R33.2@122.253,162.8 122.2,162.747 C27.2@122.2,161.3 122.2,160.7 122.5,160.4 127.3,160.4 128.101,159.599 U4.3@128.101,158.315 128.2,158.215 v1(128.2,156.8) ; v1(134.2,108.7) 135.7,108.7 136.6,107.8 137.34,107.8 Q5.3@137.39,107.75 ; v1(135,177.8) R55.2@135,178.247 136.553,179.8 SW2.1@138.125,179.8
  Bottom Layer w0.2: v1(134.2,108.7) 131.1,108.7 127.302,112.498 115.675,112.498 114.8,113.373 114.8,117 114.675,117.125 114.675,117.325 114.304,117.696 114.304,121.996 114.104,122.196 114.104,138.525 114.898,139.319 114.898,141.502 113.9,142.5 113.9,149.046 117.15,152.296 126.696,152.296 128.5,154.1 128.5,156.5 v1(128.2,156.8) 128.2,171.298 128.7,171.798 134.598,171.798 135,172.2 v1(135,177.8)
GDR: CN1.23 Q1.1 R1.2 | length 12.8
  Top Layer w0.2: CN1.23@131.235,123.789 131.235,125.364 132.556,126.685 133.456,126.685 133.886,127.114 R1.2@133.886,128.461 132.986,129.361 132.986,132.214 132.4,132.8 132.4,133.4 132.136,133.664 131.662,133.664 Q1.1@131.575,133.752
